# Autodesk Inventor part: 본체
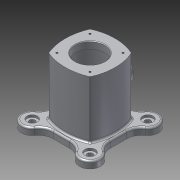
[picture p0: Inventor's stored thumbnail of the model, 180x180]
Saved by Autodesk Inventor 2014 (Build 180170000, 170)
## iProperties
Created: 2016-05
Part Number: 본체
Material: Aluminum 6061
Document SubType Name: Modeling
Designer: user
Density: 2.71 g/cm^3
Appearance: Aluminum - Flat
Mass: 1100.96 g
Surface Area: 863.766 cm^2
Volume: 406.257 cm^3
Author: user
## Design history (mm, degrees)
sketch "Sketch1"
  geometry: L1 (0, 0)-(108.894, 0); L2 (0, 0)-(113.137, 0); L3 (0, 0)-(137.179, 0); L4 (0, 0)-(113.137, 0); L5 (49, 14.162)-(49, -14.162); L6 (14.162, -49)-(-14.162, -49); L7 (-49, -14.162)-(-49, 14.162); L8 (14.162, 49)-(-14.162, 49); A1 r 18 centre (49.497, 49.497) between (59.754, 34.706) and (34.706, 59.754); A2 r 18 centre (-49.497, 49.497) between (-34.706, 59.754) and (-59.754, 34.706); A3 r 18 centre (49.497, -49.497) between (34.706, -59.754) and (59.754, -34.706); A4 r 18 centre (-49.497, -49.497) between (-59.754, -34.706) and (-34.706, -59.754); A5 r 25 centre (-74, 14.162) between (-49, 14.162) and (-59.754, 34.706); A6 r 25 centre (-74, -14.162) between (-59.754, -34.706) and (-49, -14.162); A7 r 25 centre (-14.162, -74) between (-14.162, -49) and (-34.706, -59.754); A8 r 25 centre (14.162, -74) between (34.706, -59.754) and (14.162, -49); A9 r 25 centre (74, -14.162) between (49, -14.162) and (59.754, -34.706); A10 r 25 centre (74, 14.162) between (59.754, 34.706) and (49, 14.162); A11 r 25 centre (-14.162, 74) between (-34.706, 59.754) and (-14.162, 49); A12 r 25 centre (14.162, 74) between (14.162, 49) and (34.706, 59.754); 9 further points
  constraints: 30 point on circle, 16 end point, 12 centre point, 12 tangent, 6 point on line, 5 equal radius, 4 horizontal, 1 horizontal alignment, 1 midpoint, 1 parallel, 1 vertical alignment
  dimensions: "d3" = 36 diameter of A1; "d9" = 36 diameter of A2; "d10" = 36 diameter of A3; "d11" = 36 diameter of A4; "d14" = 25 radius of A5
extrude "Extrusion1" new body sketch "Sketch1" distance "d15" = 12; taper "d16" = 0 deg
sketch "Sketch2"
  geometry: L1 (0, 0)-(50, 0); L2 (0, 0)-(50, 0); L3 (0, 0)-(50, 0); L4 (0, 0)-(50, 0); A1 r 85.579 centre (0, -42.579) between (35.355, 35.355) and (-35.355, 35.355); A2 r 85.579 centre (-42.579, 0) between (35.355, -35.355) and (35.355, 35.355); A3 r 90.136 centre (47.557, 0) between (-35.355, 35.355) and (-35.355, -35.355); A4 r 90.136 centre (0, 47.557) between (-35.355, -35.355) and (35.355, -35.355); 2 further points
  constraints: 11 point on circle, 8 end point, 4 centre point, 4 horizontal, 1 horizontal alignment, 1 vertical alignment
  dimensions: "d19" = 50 distance of L1.start A1.start; "d21" = 50 distance of L1.start A3.end; "d23" = 50 distance of L1.start A2.start; "d25" = 50 distance of L1.start A1.end
extrude "Extrusion2" join sketch "Sketch2" distance "d27" = 98; taper "d28" = 0 deg
workplane "Work Plane1"
sketch "Sketch3"
  geometry: L1 (67.497, 12)-(34.706, 12) reference; C1 r 20 at (0, 61); 2 further points
  constraints: 1 centre point
  dimensions: "d30" = 40 diameter of C1; "d31" = 49 distance from line of L1 C1.centre
extrude "Extrusion3" join sketch "Sketch3" distance "d32" = 40 (= d30); taper "d33" = 10 deg
sketch "Sketch4"
  geometry: C1 r 25 at (0, 0); 1 further point
  constraints: 1 centre point, 1 coincident
  dimensions: "d34" = 50 diameter of C1
extrude "Extrusion4" cut sketch "Sketch4" distance "d35" = 12; taper "d36" = 0 deg
sketch "Sketch5"
  geometry: C1 r 25 at (0, 0) reference; C2 r 35 at (0, 0)
  constraints: 1 centre point, 1 coincident
  dimensions: "d37" = 70 diameter of C2
extrude "Extrusion5" cut sketch "Sketch5" distance "d38" = 86; taper "d39" = 0 deg
sketch "Sketch6"
  geometry: C1 r 25 at (0, 0); 1 further point
  constraints: 1 centre point, 1 coincident
  dimensions: "d40" = 50 diameter of C1
extrude "Extrusion6" cut sketch "Sketch6" distance "d41" = 12; taper "d42" = 0 deg
sketch "Sketch7"
  geometry: C1 r 20 at (0, 0) reference; C2 r 15 at (0, 0); 1 further point
  constraints: 1 centre point, 1 coincident
  dimensions: "d43" = 30 diameter of C2
extrude "Extrusion7" cut sketch "Sketch7" distance "d44" = 8; taper "d45" = 0 deg
sketch "Sketch8"
  geometry: C1 r 15 at (0, 0) reference; C2 r 12.5 at (0, 0); 1 further point
  constraints: 1 centre point, 1 coincident
  dimensions: "d46" = 25 diameter of C2
extrude "Extrusion8" cut sketch "Sketch8" stored distance "d47" = 8; taper "d48" = 0 deg
sketch "Sketch10"
  geometry: L1 (0, 0)-(69.296, 0); C1 r 25 at (0, 0) reference; 1 further point
  constraints: 2 end point, 1 coincident, 1 horizontal
hole "Hole2" sketch "Sketch10" at (28.284, 28.284) diameter "d61" = 3.242; stored, may be unused: countersink angle "d65" = 90 deg, drill point angle "d67" = 118 deg; dims "d62" = 7, "d63" = 18, "d64" = 4, "d66" = 10
pattern_circular "Circular Pattern2" dims angle "d69" = 360 deg
sketch "Sketch11"
  geometry: L1 (0, 0)-(114.551, 0); C1 r 25 at (0, 0) reference; 1 further point
  constraints: 2 end point, 1 coincident, 1 horizontal
hole "Hole3" sketch "Sketch11" at (28.284, 28.284) diameter "d73" = 3.242; stored, may be unused: countersink angle "d77" = 90 deg, drill point angle "d79" = 118 deg; dims "d74" = 7, "d75" = 18, "d76" = 4, "d78" = 10
pattern_circular "Circular Pattern3" dims angle "d81" = 360 deg
chamfer "Chamfer1" distance "d83" = 1; stored, may be unused: second distance "d84" = 2, angle "d85" = 45 deg
fillet "Fillet1" dims "d86" = 3
chamfer "Chamfer2" distance "d87" = 1; stored, may be unused: second distance "d88" = 2, angle "d89" = 45 deg
fillet "Fillet2" dims "d90" = 3
fillet "Fillet3" dims "d91" = 3
fillet "Fillet4" dims "d92" = 3
fillet "Fillet5" dims "d93" = 3
sketch "Sketch12"
  geometry: L1 (46, 14.162)-(46, 0) reference; L2 (0, 46)-(14.162, 46) reference; C1 r 9 at (-49.497, 49.497); A1 r 15 centre (-49.497, 49.497) between (-37.171, 58.045) and (-58.045, 37.171) reference; A2 r 28 centre (74, 14.162) between (58.045, 37.171) and (46, 14.162) reference; A3 r 15 centre (49.497, 49.497) between (58.045, 37.171) and (37.171, 58.045) reference; A4 r 28 centre (14.162, 74) between (14.162, 46) and (37.171, 58.045) reference; A5 r 88.579 centre (0, -42.579) between (35.487, 38.581) and (0, 46) reference; A6 r 6 centre (33.083, 33.083) between (38.581, 35.487) and (35.487, 38.581) reference; A7 r 88.579 centre (-42.579, 0) between (46, 0) and (38.581, 35.487) reference; 1 further point
  constraints: 1 centre point, 1 coincident
  dimensions: "d94" = 18 diameter of C1
extrude "Extrusion9" cut sketch "Sketch12" distance "d95" = 4; taper "d96" = 0 deg
sketch "Sketch13"
  geometry: C1 r 9 at (0, 0) reference; C2 r 5 at (0, 0); 1 further point
  constraints: 1 centre point, 1 coincident
  dimensions: "d97" = 10 diameter of C2
extrude "Extrusion10" cut sketch "Sketch13" distance "d98" = 8; taper "d99" = 0 deg
pattern_circular "Circular Pattern4" dims angle "d101" = 360 deg
workplane "Work Plane2"
sketch "Sketch15"
  geometry: L1 (-23.235, 81.739)-(-23.235, 40.261); L2 (-23.235, 40.261)-(-34.765, 40.261); L3 (-34.765, 40.261)-(-34.765, 81.739); L4 (-34.765, 81.739)-(-23.235, 81.739); L5 (34.248, 110)-(-34.285, 110) reference; 4 further points
  constraints: 2 midpoint, 1 horizontal alignment, 1 vertical alignment, 2 other
  dimensions: "d108" = 29 horizontal distance of point (0, 0) point (-29, 61); "d109" = 49 distance from line of point (-29, 61) L5
emboss "Emboss2" sketch "Sketch15" dims "d3" = 36, "d9" = 36, "d10" = 36, "d11" = 36, "d14" = 25, "d110" = 0.5, "d111" = 0
body "Solid1"
node "Projected Loop1"
other parameters: "d29" = 55, "d103" = 43
